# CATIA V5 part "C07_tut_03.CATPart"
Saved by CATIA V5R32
Part number: Part1
Bounding box of the stored display mesh (mm): x 0 to 108, y -52.5 to 52.5, z -52.5 to 52.5
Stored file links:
  D:\PROJECTS\Project 2022\CATIA V5 6R 2022\Resources\Tutorial Files\c07_catia_v5_6r2022_tut\C07_tut_03.CATPart
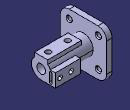
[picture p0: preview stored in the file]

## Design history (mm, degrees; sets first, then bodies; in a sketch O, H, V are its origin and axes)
Body1 (main body)
  Sketch1 on yz-plane, origin (0, 0, 0), H (0, 1, 0), V (0, 0, 1)
    line L1 (52.5, 32.5) -> (52.5, -32.5)
    line L2 (32.5, -52.5) -> (-32.5, -52.5)
    line L3 (-52.5, -32.5) -> (-52.5, 32.5)
    line L4 (-32.5, 52.5) -> (32.5, 52.5)
    point P1 (52.5, 52.5)
    point P2 (52.5, -52.5)
    point P3 (-52.5, -52.5)
    arc A1 centre (32.5, 32.5) radius 20 from (52.5, 32.5) to (32.5, 52.5) ccw
    arc A2 centre (32.5, -32.5) radius 20 from (52.5, -32.5) to (32.5, -52.5) cw
    arc A3 centre (-32.5, -32.5) radius 20 from (-32.5, -52.5) to (-52.5, -32.5) cw
    arc A4 centre (-32.5, 32.5) radius 20 from (-52.5, 32.5) to (-32.5, 52.5) cw
    distance P1 P2 = 105
    radius A1 = 20
    distance P2 P3 = 105
    radius A2 = 20
    radius A3 = 20
    radius A4 = 20
    vertical: L1 V, L3 V
    horizontal: L2 H, L4 H
    equidistance: L1 L3 O, L2 L4 O
    coincidence: L1 P1, L4 P1, L1 P2, L2 P2, L2 P3, L3 P3
    tangency: A1 L1, A1 L4, A2 L1, A2 L2, A3 L2, A3 L3, A4 L3, A4 L4
  Pad1: profile Sketch1, direction (1, 0, 0), length 12
  Sketch2 on face of Pad1, origin (12, 0, 0), H (0, 1, 0), V (0, 0, 1)
    circle A1 centre (0, 0) radius 22
    radius A1 = 22
  Pad2: profile Sketch2, direction (1, 0, 0), length 96
  Sketch3 on face of Pad2, origin (108, 0, 0), H (0, 1, 0), V (0, 0, 1)
    point P1 (-15, 16.0935)
    line L1 (-15, 16.0935) -> (-15, 25)
    line L2 (-15, 25) -> (15, 25)
    line L3 (15, 25) -> (15, 16.0935)
    point P4 (15, 16.0935)
    axis line L4 (0, 0) -> (0, 25)
    point P5 (0, 25)
    reference projected circle E1 centre (0, 0) radius 22 from edge [face of Pad2 | face of Pad2]
    reference projected circle E2 centre (0, 0) radius 22 from edge [face of Pad2 | face of Pad2]
    projected circle E3 centre (0, 0) radius 22 from edge [face of Pad2 | face of Pad2]
    projected arc E4 centre (0, 0) radius 22 from (15, 16.0935) to (-15, 16.0935) ccw from edge [face of Pad2 | face of Pad2]
    length L2 = 30
    distance H L2 = 25
    vertical: L1 V, L3 V, L4 V
    horizontal: L2 H
    midpoint: P5 L2
    coincidence: P4 E1, P1 E2
  Pad3: profile Sketch3, direction (-1, 0, 0), length 76
  Sketch4 on face of Pad2, origin (108, 0, 0), H (0, 1, 0), V (0, 0, 1)
    point P1 (0, -22)
    line L1 (0, -22) -> (32, -22)
    line L2 (32, -22) -> (32, 8)
    line L3 (32, 8) -> (20.4939, 8)
    point P4 (20.4939, 8)
    reference projected circle E1 centre (0, 0) radius 22 from edge of Pad2
    reference projected circle E2 centre (0, 0) radius 22 from edge [face of Pad2 | face of Pad2]
    reference projected circle E3 centre (0, 0) radius 22 from edge [face of Pad2 | face of Pad2]
    projected arc E4 centre (0, 0) radius 22 from (-15, 16.0935) to (15, 16.0935) ccw from edge of Pad3
    projected arc E5 centre (0, 0) radius 22 from (0, -22) to (20.4939, 8) ccw from edge of Pad3
    length L2 = 30
    distance V L2 = 32
    coincidence: P1 V, P4 E1, P1 E2
    horizontal: L1 H, L3 H
    vertical: L2 V
    tangency: L1 E3
  Pad4: profile Sketch4, direction (-1, 0, 0), length 57
  Sketch5 on face of Pad2, origin (108, 0, 0), H (0, 1, 0), V (0, 0, 1)
    line L1 (24.5, 2.5) -> (24.5, -16.5)
    line L2 (18.5, -16.5) -> (18.5, 2.5)
    point P4 (18.5, -16.5)
    arc A1 centre (21.5, 2.5) radius 3 from (24.5, 2.5) to (18.5, 2.5) ccw
    point P5 (21.5, 2.5)
    arc A2 centre (21.5, -16.5) radius 3 from (18.5, -16.5) to (24.5, -16.5) ccw
    point P6 (21.5, -16.5)
    point P7 (18.5, -16.5)
    reference projected line E1 (52.5, -32.5) -> (52.5, 32.5) from edge [face of Pad1 from Sketch1.L1 | end face of Pad1]
    reference projected line E2 (-32.5, -52.5) -> (32.5, -52.5) from edge [face of Pad1 from Sketch1.L2 | end face of Pad1]
    length L1 = 19
    distance L1 P5 = 3
    distance L2 E1 = 34
    distance P6 E2 = 36
    vertical: L1 V, L2 V
    tangency: A1 L1, A2 L1, A2 L2, A1 L2
    coincidence: P4 P7
  Pocket1: profile Sketch5, direction (-1, 0, 0), length 50
  Sketch6 on face of Pad2, origin (108, 0, 0), H (0, 1, 0), V (0, 0, 1)
    point P1 (0, 0)
    coincidence: P1 O
  Hole1: placed by Sketch6, at (108, 0, 0) direction (-1, 0, 0), diameter 20, up to end face of Pad1
  Sketch7 on face of Pad3, origin (90.7325, -5.9449, 25), H (1, 0, 0), V (0, 1, 0)
    point P1 (1.2675, 5.9449)
    reference projected line E1 (17.2675, -9.0551) -> (-58.7325, -9.0551) from edge [face of Pad3 | face of Pad3]
    reference projected line E2 (17.2675, 20.9449) -> (17.2675, -9.0551) from edge [face of Pad3 | face of Pad3]
    distance P1 E1 = 15
    distance P1 E2 = 16
  Hole2: placed by Sketch7, at (92, 0, 25) direction (0, 0, -1), diameter 12, depth 33.0037, threaded, thread diameter 13.2, thread depth 10, pitch 1
  RectPattern1: of Hole2, direction 1 instances 2, spacing 44, along edge [face of Pad3 | face of Pad3]
  Sketch8 on face of Pad4, origin (86.2721, 32, -2.7131), H (1, 0, 0), V (0, 0, -1)
    point P1 (10.7279, 4.2869)
    reference projected line E1 (21.7279, 19.2869) -> (-35.2721, 19.2869) from edge [face of Pad4 | face of Pad4]
    reference projected line E2 (21.7279, 19.2869) -> (21.7279, -10.7131) from edge [face of Pad4 | face of Pad4]
    distance P1 E1 = 15
    distance E2 P1 = 11
  Hole3: placed by Sketch8, at (97, 32, -7) direction (0, -1, 0), diameter 10, through (limit type 6)
  RectPattern2: of Hole3, direction 1 instances 2, spacing 25, along edge [face of Pad4 | face of Pad4], direction 2 instances 2, spacing 76
  Sketch9 on face of Pad1, origin (12, -36.1764, 22.8739), H (0, 1, 0), V (0, 0, 1)
    point P1 (3.6764, -55.3739)
    reference projected line E1 (-16.3236, 9.6261) -> (-16.3236, -55.3739) from edge [face of Pad1 | face of Pad1]
    reference projected line E2 (3.6764, -75.3739) -> (68.6764, -75.3739) from edge [face of Pad1 | face of Pad1]
    distance P1 E1 = 20
    distance E2 P1 = 20
  Hole4: placed by Sketch9, at (12, -32.5, -32.5) direction (-1, 0, 0), diameter 10, through (limit type 3), countersink depth 2, countersink angle 90
  RectPattern3: of Hole4, direction 1 instances 2, spacing 66, along edge [face of Pad1 | face of Pad1], direction 2 instances 2, spacing 66, along edge [face of Pad1 | face of Pad1] reversed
